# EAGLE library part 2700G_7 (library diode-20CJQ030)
Intel® 2700G7 Multimedia Graphic Accelerator with 16MB SDRAM 14 mm x 14 mm, 0.65 mm ball pitch 364 ball BGA package optimized for space constrained handheld devices Features: Advanced Packages -14 mm x 14 mm, 0.65 mm ball pitch, 364 ball BGA package optimized for space constrained handheld devices Low Power - Up to VGA (640x480x16 bpp) refresh from integrated frame buffer (2700G5 Multimedia Accelerator only) - Extensive clock gating of both registers and modules - Low voltage core (1.2 V) - Low voltage I/O (1.8 V) - 0.13 micron process technology - Partial and one-shot display refresh support Low Power, High Performance Video Acceleration - Accelerated MPEG 2 video decode, 720 x 480 resolution, 30+ fps - Accelerated MPEG 4 video decode, 640 x 480, 30+ fps - Accelerated WMV* video decode, 640 x 480, 30+ fps - Hardware accelerated Inverse Discrete Cosine Transforms (IDCT) - Hardware accelerated motion compensation - Hardware accelerated color space conversion - Hardware accelerated scaling Low Power, High Performance Graphics Acceleration - 2D and 3D acceleration - Up to 75 MHz, 32-bit graphics engine - 150M pixels per second (pps) fill rate for 2D - 831K triangles per second (tps) processing capability for 3D Packaged Memory Solutions - Integrated 704 KB on die memory - Stacked high-speed SDRAM for local memory - High-speed SDRAM local memory interface -- 16 MB SDRAM at 100 MHz -- 1.8 V SDRAM support -- Low-power SDRAM support Accelerated Dual Display - Simultaneous displays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
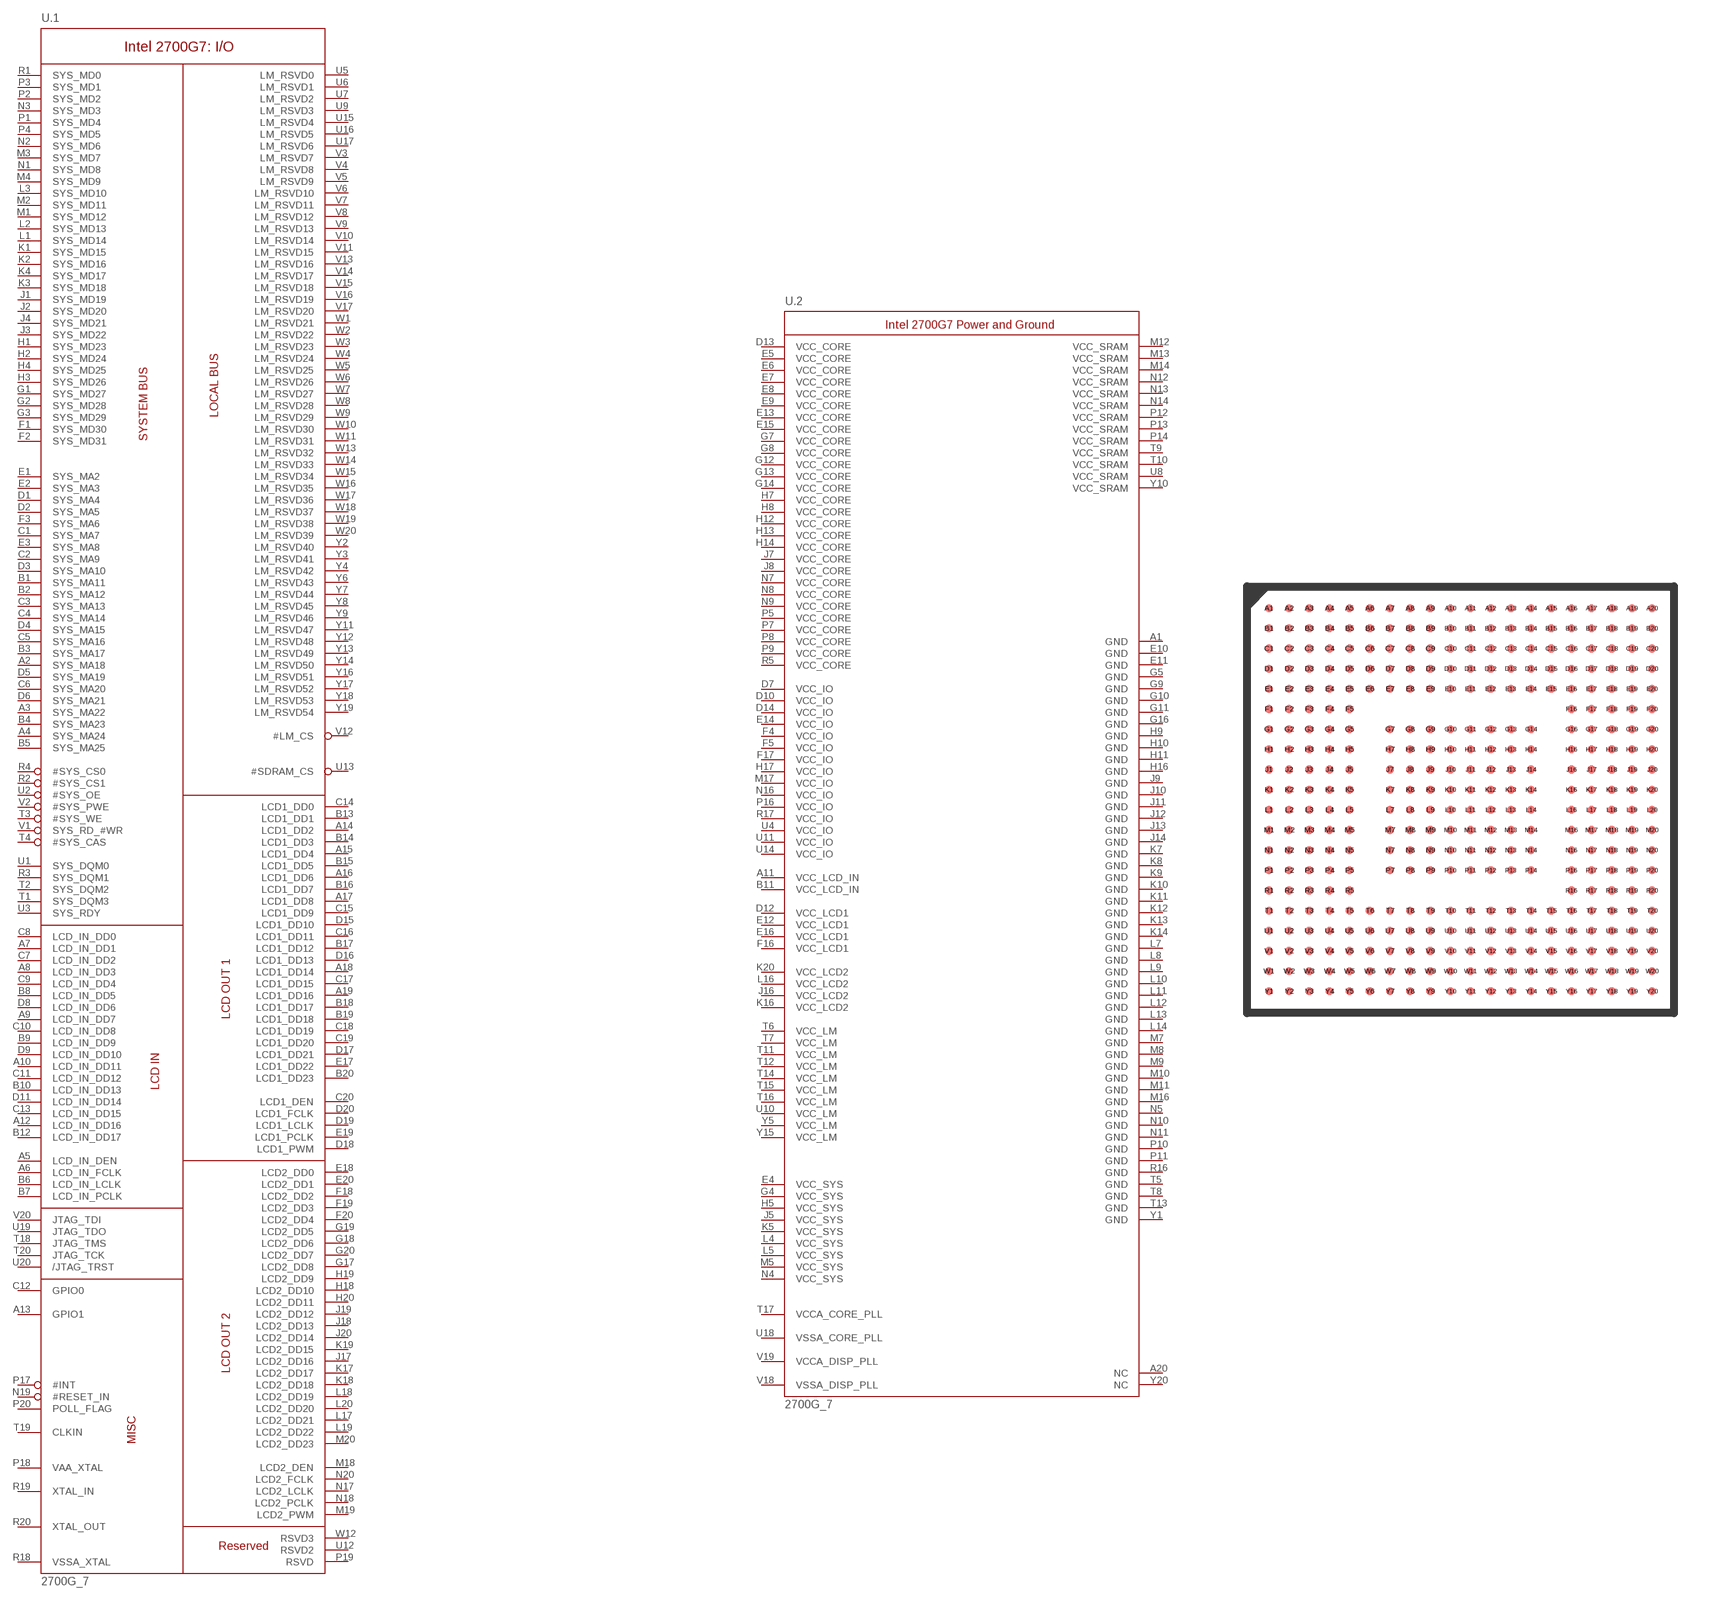
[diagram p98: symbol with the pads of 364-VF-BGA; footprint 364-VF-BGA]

Designator prefix U; gates .1=2700G7_PERIPHERALS .2=2700G7_POWER

## 2700G_7  [364-VF-BGA]
A1  .2:GND  pwr
A2  .1:SYS_MA18  in
A3  .1:SYS_MA22  in
A4  .1:SYS_MA24  in
A5  .1:LCD_IN_DEN  in
A6  .1:LCD_IN_FCLK  in
A7  .1:LCD_IN_DD1  in
A8  .1:LCD_IN_DD3  in
A9  .1:LCD_IN_DD7  in
A10  .1:LCD_IN_DD11  in
A11  .2:VCC_LCD_IN  pwr
A12  .1:LCD_IN_DD16  in
A13  .1:GPIO1
A14  .1:LCD1_DD2  out
A15  .1:LCD1_DD4  out
A16  .1:LCD1_DD6  out
A17  .1:LCD1_DD8  out
A18  .1:LCD1_DD14  out
A19  .1:LCD1_DD16  out
A20  .2:NC  nc
B1  .1:SYS_MA11  in
B2  .1:SYS_MA12  in
B3  .1:SYS_MA17  in
B4  .1:SYS_MA23  in
B5  .1:SYS_MA25  in
B6  .1:LCD_IN_LCLK  in
B7  .1:LCD_IN_PCLK  in
B8  .1:LCD_IN_DD5  in
B9  .1:LCD_IN_DD9  in
B10  .1:LCD_IN_DD13  in
B11  .2:VCC_LCD_IN  pwr
B12  .1:LCD_IN_DD17  in
B13  .1:LCD1_DD1  out
B14  .1:LCD1_DD3  out
B15  .1:LCD1_DD5  out
B16  .1:LCD1_DD7  out
B17  .1:LCD1_DD12  out
B18  .1:LCD1_DD17  out
B19  .1:LCD1_DD18  out
B20  .1:LCD1_DD23  out
C1  .1:SYS_MA7  in
C2  .1:SYS_MA9  in
C3  .1:SYS_MA13  in
C4  .1:SYS_MA14  in
C5  .1:SYS_MA16  in
C6  .1:SYS_MA20  in
C7  .1:LCD_IN_DD2  in
C8  .1:LCD_IN_DD0  in
C9  .1:LCD_IN_DD4  in
C10  .1:LCD_IN_DD8  in
C11  .1:LCD_IN_DD12  in
C12  .1:GPIO0
C13  .1:LCD_IN_DD15  in
C14  .1:LCD1_DD0  out
C15  .1:LCD1_DD9  out
C16  .1:LCD1_DD11  out
C17  .1:LCD1_DD15  out
C18  .1:LCD1_DD19  out
C19  .1:LCD1_DD20  out
C20  .1:LCD1_DEN  out
D1  .1:SYS_MA4  in
D2  .1:SYS_MA5  in
D3  .1:SYS_MA10  in
D4  .1:SYS_MA15  in
D5  .1:SYS_MA19  in
D6  .1:SYS_MA21  in
D7  .2:VCC_IO  pwr
D8  .1:LCD_IN_DD6  in
D9  .1:LCD_IN_DD10  in
D10  .2:VCC_IO  pwr
D11  .1:LCD_IN_DD14  in
D12  .2:VCC_LCD1  pwr
D13  .2:VCC_CORE  pwr
D14  .2:VCC_IO  pwr
D15  .1:LCD1_DD10  out
D16  .1:LCD1_DD13  out
D17  .1:LCD1_DD21  out
D18  .1:LCD1_PWM  out
D19  .1:LCD1_LCLK  out
D20  .1:LCD1_FCLK  out
E1  .1:SYS_MA2  in
E2  .1:SYS_MA3  in
E3  .1:SYS_MA8  in
E4  .2:VCC_SYS  pwr
E5  .2:VCC_CORE  pwr
E6  .2:VCC_CORE  pwr
E7  .2:VCC_CORE  pwr
E8  .2:VCC_CORE  pwr
E9  .2:VCC_CORE  pwr
E10  .2:GND  pwr
E11  .2:GND  pwr
E12  .2:VCC_LCD1  pwr
E13  .2:VCC_CORE  pwr
E14  .2:VCC_IO  pwr
E15  .2:VCC_CORE  pwr
E16  .2:VCC_LCD1  pwr
E17  .1:LCD1_DD22  out
E18  .1:LCD2_DD0  out
E19  .1:LCD1_PCLK  out
E20  .1:LCD2_DD1  out
F1  .1:SYS_MD30
F2  .1:SYS_MD31
F3  .1:SYS_MA6  in
F4  .2:VCC_IO  pwr
F5  .2:VCC_IO  pwr
F16  .2:VCC_LCD1  pwr
F17  .2:VCC_IO  pwr
F18  .1:LCD2_DD2  out
F19  .1:LCD2_DD3  out
F20  .1:LCD2_DD4  out
G1  .1:SYS_MD27
G2  .1:SYS_MD28
G3  .1:SYS_MD29
G4  .2:VCC_SYS  pwr
G5  .2:GND  pwr
G7  .2:VCC_CORE  pwr
G8  .2:VCC_CORE  pwr
G9  .2:GND  pwr
G10  .2:GND  pwr
G11  .2:GND  pwr
G12  .2:VCC_CORE  pwr
G13  .2:VCC_CORE  pwr
G14  .2:VCC_CORE  pwr
G16  .2:GND  pwr
G17  .1:LCD2_DD8  out
G18  .1:LCD2_DD6  out
G19  .1:LCD2_DD5  out
G20  .1:LCD2_DD7  out
H1  .1:SYS_MD23
H2  .1:SYS_MD24
H3  .1:SYS_MD26
H4  .1:SYS_MD25
H5  .2:VCC_SYS  pwr
H7  .2:VCC_CORE  pwr
H8  .2:VCC_CORE  pwr
H9  .2:GND  pwr
H10  .2:GND  pwr
H11  .2:GND  pwr
H12  .2:VCC_CORE  pwr
H13  .2:VCC_CORE  pwr
H14  .2:VCC_CORE  pwr
H16  .2:GND  pwr
H17  .2:VCC_IO  pwr
H18  .1:LCD2_DD10  out
H19  .1:LCD2_DD9  out
H20  .1:LCD2_DD11  out
J1  .1:SYS_MD19
J2  .1:SYS_MD20
J3  .1:SYS_MD22
J4  .1:SYS_MD21
J5  .2:VCC_SYS  pwr
J7  .2:VCC_CORE  pwr
J8  .2:VCC_CORE  pwr
J9  .2:GND  pwr
J10  .2:GND  pwr
J11  .2:GND  pwr
J12  .2:GND  pwr
J13  .2:GND  pwr
J14  .2:GND  pwr
J16  .2:VCC_LCD2  pwr
J17  .1:LCD2_DD16  out
J18  .1:LCD2_DD13  out
J19  .1:LCD2_DD12  out
J20  .1:LCD2_DD14  out
K1  .1:SYS_MD15
K2  .1:SYS_MD16
K3  .1:SYS_MD18
K4  .1:SYS_MD17
K5  .2:VCC_SYS  pwr
K7  .2:GND  pwr
K8  .2:GND  pwr
K9  .2:GND  pwr
K10  .2:GND  pwr
K11  .2:GND  pwr
K12  .2:GND  pwr
K13  .2:GND  pwr
K14  .2:GND  pwr
K16  .2:VCC_LCD2  pwr
K17  .1:LCD2_DD17  out
K18  .1:LCD2_DD18  out
K19  .1:LCD2_DD15  out
K20  .2:VCC_LCD2  pwr
L1  .1:SYS_MD14
L2  .1:SYS_MD13
L3  .1:SYS_MD10
L4  .2:VCC_SYS  pwr
L5  .2:VCC_SYS  pwr
L7  .2:GND  pwr
L8  .2:GND  pwr
L9  .2:GND  pwr
L10  .2:GND  pwr
L11  .2:GND  pwr
L12  .2:GND  pwr
L13  .2:GND  pwr
L14  .2:GND  pwr
L16  .2:VCC_LCD2  pwr
L17  .1:LCD2_DD21  out
L18  .1:LCD2_DD19  out
L19  .1:LCD2_DD22  out
L20  .1:LCD2_DD20  out
M1  .1:SYS_MD12
M2  .1:SYS_MD11
M3  .1:SYS_MD7
M4  .1:SYS_MD9
M5  .2:VCC_SYS  pwr
M7  .2:GND  pwr
M8  .2:GND  pwr
M9  .2:GND  pwr
M10  .2:GND  pwr
M11  .2:GND  pwr
M12  .2:VCC_SRAM  pwr
M13  .2:VCC_SRAM  pwr
M14  .2:VCC_SRAM  pwr
M16  .2:GND  pwr
M17  .2:VCC_IO  pwr
M18  .1:LCD2_DEN  out
M19  .1:LCD2_PWM  out
M20  .1:LCD2_DD23  out
N1  .1:SYS_MD8
N2  .1:SYS_MD6
N3  .1:SYS_MD3
N4  .2:VCC_SYS  pwr
N5  .2:GND  pwr
N7  .2:VCC_CORE  pwr
N8  .2:VCC_CORE  pwr
N9  .2:VCC_CORE  pwr
N10  .2:GND  pwr
N11  .2:GND  pwr
N12  .2:VCC_SRAM  pwr
N13  .2:VCC_SRAM  pwr
N14  .2:VCC_SRAM  pwr
N16  .2:VCC_IO  pwr
N17  .1:LCD2_LCLK  out
N18  .1:LCD2_PCLK  out
N19  .1:#RESET_IN  in
N20  .1:LCD2_FCLK  out
P1  .1:SYS_MD4
P2  .1:SYS_MD2
P3  .1:SYS_MD1
P4  .1:SYS_MD5
P5  .2:VCC_CORE  pwr
P7  .2:VCC_CORE  pwr
P8  .2:VCC_CORE  pwr
P9  .2:VCC_CORE  pwr
P10  .2:GND  pwr
P11  .2:GND  pwr
P12  .2:VCC_SRAM  pwr
P13  .2:VCC_SRAM  pwr
P14  .2:VCC_SRAM  pwr
P16  .2:VCC_IO  pwr
P17  .1:#INT  out
P18  .1:VAA_XTAL  pwr
P19  .1:RSVD  in
P20  .1:POLL_FLAG  out
R1  .1:SYS_MD0
R2  .1:#SYS_CS1  in
R3  .1:SYS_DQM1  in
R4  .1:#SYS_CS0  in
R5  .2:VCC_CORE  pwr
R16  .2:GND  pwr
R17  .2:VCC_IO  pwr
R18  .1:VSSA_XTAL  pwr
R19  .1:XTAL_IN  in
R20  .1:XTAL_OUT  out
T1  .1:SYS_DQM3  in
T2  .1:SYS_DQM2  in
T3  .1:#SYS_WE  in
T4  .1:#SYS_CAS  in
T5  .2:GND  pwr
T6  .2:VCC_LM  pwr
T7  .2:VCC_LM  pwr
T8  .2:GND  pwr
T9  .2:VCC_SRAM  pwr
T10  .2:VCC_SRAM  pwr
T11  .2:VCC_LM  pwr
T12  .2:VCC_LM  pwr
T13  .2:GND  pwr
T14  .2:VCC_LM  pwr
T15  .2:VCC_LM  pwr
T16  .2:VCC_LM  pwr
T17  .2:VCCA_CORE_PLL  pwr
T18  .1:JTAG_TMS  in
T19  .1:CLKIN  in
T20  .1:JTAG_TCK  in
U1  .1:SYS_DQM0  in
U2  .1:#SYS_OE  in
U3  .1:SYS_RDY  out
U4  .2:VCC_IO  pwr
U5  .1:LM_RSVD0
U6  .1:LM_RSVD1
U7  .1:LM_RSVD2
U8  .2:VCC_SRAM  pwr
U9  .1:LM_RSVD3
U10  .2:VCC_LM  pwr
U11  .2:VCC_IO  pwr
U12  .1:RSVD2  in
U13  .1:#SDRAM_CS  out
U14  .2:VCC_IO  pwr
U15  .1:LM_RSVD4
U16  .1:LM_RSVD5
U17  .1:LM_RSVD6
U18  .2:VSSA_CORE_PLL  pwr
U19  .1:JTAG_TDO  out
U20  .1:/JTAG_TRST  in
V1  .1:SYS_RD_#WR  in
V2  .1:#SYS_PWE  in
V3  .1:LM_RSVD7
V4  .1:LM_RSVD8
V5  .1:LM_RSVD9
V6  .1:LM_RSVD10
V7  .1:LM_RSVD11
V8  .1:LM_RSVD12
V9  .1:LM_RSVD13
V10  .1:LM_RSVD14
V11  .1:LM_RSVD15
V12  .1:#LM_CS  out
V13  .1:LM_RSVD16
V14  .1:LM_RSVD17
V15  .1:LM_RSVD18
V16  .1:LM_RSVD19
V17  .1:LM_RSVD20
V18  .2:VSSA_DISP_PLL  pwr
V19  .2:VCCA_DISP_PLL  pwr
V20  .1:JTAG_TDI  in
W1  .1:LM_RSVD21
W2  .1:LM_RSVD22
W3  .1:LM_RSVD23
W4  .1:LM_RSVD24
W5  .1:LM_RSVD25
W6  .1:LM_RSVD26
W7  .1:LM_RSVD27
W8  .1:LM_RSVD28
W9  .1:LM_RSVD29
W10  .1:LM_RSVD30
W11  .1:LM_RSVD31
W12  .1:RSVD3  in
W13  .1:LM_RSVD32  out
W14  .1:LM_RSVD33  out
W15  .1:LM_RSVD34  out
W16  .1:LM_RSVD35  out
W17  .1:LM_RSVD36  out
W18  .1:LM_RSVD37  out
W19  .1:LM_RSVD38  out
W20  .1:LM_RSVD39  out
Y1  .2:GND  pwr
Y2  .1:LM_RSVD40  out
Y3  .1:LM_RSVD41  out
Y4  .1:LM_RSVD42  out
Y5  .2:VCC_LM  pwr
Y6  .1:LM_RSVD43  out
Y7  .1:LM_RSVD44  out
Y8  .1:LM_RSVD45  out
Y9  .1:LM_RSVD46  out
Y10  .2:VCC_SRAM  pwr
Y11  .1:LM_RSVD47  out
Y12  .1:LM_RSVD48  out
Y13  .1:LM_RSVD49  out
Y14  .1:LM_RSVD50  out
Y15  .2:VCC_LM  pwr
Y16  .1:LM_RSVD51  out
Y17  .1:LM_RSVD52  out
Y18  .1:LM_RSVD53  out
Y19  .1:LM_RSVD54  out
Y20  .2:NC  nc

## Footprint 364-VF-BGA (pad centres in mm)
VF-BGA. Package 14 mm x 14 mm BGA. 364 balls spaced on a 0.65 mm ball grid (pitch) The ball diameter is 0.254 mm. (Design Guide of Intels 2700G3/5/7) Please send any comments to: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
smd 0.254 x 0.254: A1 -6.175,6.175; A2 -5.525,6.175; A3 -4.875,6.175; A4 -4.225,6.175; A5 -3.575,6.175; A6 -2.925,6.175; A7 -2.275,6.175; A8 -1.625,6.175; A9 -0.975,6.175; A10 -0.325,6.175; A11 0.325,6.175; A12 0.975,6.175; A13 1.625,6.175; A14 2.275,6.175; A15 2.925,6.175; A16 3.575,6.175; A17 4.225,6.175; A18 4.875,6.175; A19 5.525,6.175; A20 6.175,6.175; B1 -6.175,5.525; B2 -5.525,5.525; B3 -4.875,5.525; B4 -4.225,5.525; B5 -3.575,5.525; B6 -2.925,5.525; B7 -2.275,5.525; B8 -1.625,5.525; B9 -0.975,5.525; B10 -0.325,5.525; B11 0.325,5.525; B12 0.975,5.525; B13 1.625,5.525; B14 2.275,5.525; B15 2.925,5.525; B16 3.575,5.525; B17 4.225,5.525; B18 4.875,5.525; B19 5.525,5.525; B20 6.175,5.525; C1 -6.175,4.875; C2 -5.525,4.875; C3 -4.875,4.875; C4 -4.225,4.875; C5 -3.575,4.875; C6 -2.925,4.875; C7 -2.275,4.875; C8 -1.625,4.875; C9 -0.975,4.875; C10 -0.325,4.875; C11 0.325,4.875; C12 0.975,4.875; C13 1.625,4.875; C14 2.275,4.875; C15 2.925,4.875; C16 3.575,4.875; C17 4.225,4.875; C18 4.875,4.875; C19 5.525,4.875; C20 6.175,4.875; D1 -6.175,4.225; D2 -5.525,4.225; D3 -4.875,4.225; D4 -4.225,4.225; D5 -3.575,4.225; D6 -2.925,4.225; D7 -2.275,4.225; D8 -1.625,4.225; D9 -0.975,4.225; D10 -0.325,4.225; D11 0.325,4.225; D12 0.975,4.225; D13 1.625,4.225; D14 2.275,4.225; D15 2.925,4.225; D16 3.575,4.225; D17 4.225,4.225; D18 4.875,4.225; D19 5.525,4.225; D20 6.175,4.225; E1 -6.175,3.575; E2 -5.525,3.575; E3 -4.875,3.575; E4 -4.225,3.575; E5 -3.575,3.575; E6 -2.925,3.575; E7 -2.275,3.575; E8 -1.625,3.575; E9 -0.975,3.575; E10 -0.325,3.575; E11 0.325,3.575; E12 0.975,3.575; E13 1.625,3.575; E14 2.275,3.575; E15 2.925,3.575; E16 3.575,3.575; E17 4.225,3.575; E18 4.875,3.575; E19 5.525,3.575; E20 6.175,3.575; F1 -6.175,2.925; F2 -5.525,2.925; F3 -4.875,2.925; F4 -4.225,2.925; F5 -3.575,2.925; F16 3.575,2.925; F17 4.225,2.925; F18 4.875,2.925; F19 5.525,2.925; F20 6.175,2.925; G1 -6.175,2.275; G2 -5.525,2.275; G3 -4.875,2.275; G4 -4.225,2.275; G5 -3.575,2.275; G7 -2.275,2.275; G8 -1.625,2.275; G9 -0.975,2.275; G10 -0.325,2.275; G11 0.325,2.275; G12 0.975,2.275; G13 1.625,2.275; G14 2.275,2.275; G16 3.575,2.275; G17 4.225,2.275; G18 4.875,2.275; G19 5.525,2.275; G20 6.175,2.275; H1 -6.175,1.625; H2 -5.525,1.625; H3 -4.875,1.625; H4 -4.225,1.625; H5 -3.575,1.625; H7 -2.275,1.625; H8 -1.625,1.625; H9 -0.975,1.625; H10 -0.325,1.625; H11 0.325,1.625; H12 0.975,1.625; H13 1.625,1.625; H14 2.275,1.625; H16 3.575,1.625; H17 4.225,1.625; H18 4.875,1.625; H19 5.525,1.625; H20 6.175,1.625; J1 -6.175,0.975; J2 -5.525,0.975; J3 -4.875,0.975; J4 -4.225,0.975; J5 -3.575,0.975; J7 -2.275,0.975; J8 -1.625,0.975; J9 -0.975,0.975; J10 -0.325,0.975; J11 0.325,0.975; J12 0.975,0.975; J13 1.625,0.975; J14 2.275,0.975; J16 3.575,0.975; J17 4.225,0.975; J18 4.875,0.975; J19 5.525,0.975; J20 6.175,0.975; K1 -6.175,0.325; K2 -5.525,0.325; K3 -4.875,0.325; K4 -4.225,0.325; K5 -3.575,0.325; K7 -2.275,0.325; K8 -1.625,0.325; K9 -0.975,0.325; K10 -0.325,0.325; K11 0.325,0.325; K12 0.975,0.325; K13 1.625,0.325; K14 2.275,0.325; K16 3.575,0.325; K17 4.225,0.325; K18 4.875,0.325; K19 5.525,0.325; K20 6.175,0.325; L1 -6.175,-0.325; L2 -5.525,-0.325; L3 -4.875,-0.325; L4 -4.225,-0.325; L5 -3.575,-0.325; L7 -2.275,-0.325; L8 -1.625,-0.325; L9 -0.975,-0.325; L10 -0.325,-0.325; L11 0.325,-0.325; L12 0.975,-0.325; L13 1.625,-0.325; L14 2.275,-0.325; L16 3.575,-0.325; L17 4.225,-0.325; L18 4.875,-0.325; L19 5.525,-0.325; L20 6.175,-0.325; M1 -6.175,-0.975; M2 -5.525,-0.975; M3 -4.875,-0.975; M4 -4.225,-0.975; M5 -3.575,-0.975; M7 -2.275,-0.975; M8 -1.625,-0.975; M9 -0.975,-0.975; M10 -0.325,-0.975; M11 0.325,-0.975; M12 0.975,-0.975; M13 1.625,-0.975; M14 2.275,-0.975; M16 3.575,-0.975; M17 4.225,-0.975; M18 4.875,-0.975; M19 5.525,-0.975; M20 6.175,-0.975; N1 -6.175,-1.625; N2 -5.525,-1.625; N3 -4.875,-1.625; N4 -4.225,-1.625; N5 -3.575,-1.625; N7 -2.275,-1.625; N8 -1.625,-1.625; N9 -0.975,-1.625; N10 -0.325,-1.625; N11 0.325,-1.625; N12 0.975,-1.625; N13 1.625,-1.625; N14 2.275,-1.625; N16 3.575,-1.625; N17 4.225,-1.625; N18 4.875,-1.625; N19 5.525,-1.625; N20 6.175,-1.625; P1 -6.175,-2.275; P2 -5.525,-2.275; P3 -4.875,-2.275; P4 -4.225,-2.275; P5 -3.575,-2.275; P7 -2.275,-2.275; P8 -1.625,-2.275; P9 -0.975,-2.275; P10 -0.325,-2.275; P11 0.325,-2.275; P12 0.975,-2.275; P13 1.625,-2.275; P14 2.275,-2.275; P16 3.575,-2.275; P17 4.225,-2.275; P18 4.875,-2.275; P19 5.525,-2.275; P20 6.175,-2.275; R1 -6.175,-2.925; R2 -5.525,-2.925; R3 -4.875,-2.925; R4 -4.225,-2.925; R5 -3.575,-2.925; R16 3.575,-2.925; R17 4.225,-2.925; R18 4.875,-2.925; R19 5.525,-2.925; R20 6.175,-2.925; T1 -6.175,-3.575; T2 -5.525,-3.575; T3 -4.875,-3.575; T4 -4.225,-3.575; T5 -3.575,-3.575; T6 -2.925,-3.575; T7 -2.275,-3.575; T8 -1.625,-3.575; T9 -0.975,-3.575; T10 -0.325,-3.575; T11 0.325,-3.575; T12 0.975,-3.575; T13 1.625,-3.575; T14 2.275,-3.575; T15 2.925,-3.575; T16 3.575,-3.575; T17 4.225,-3.575; T18 4.875,-3.575; T19 5.525,-3.575; T20 6.175,-3.575; U1 -6.175,-4.225; U2 -5.525,-4.225; U3 -4.875,-4.225; U4 -4.225,-4.225; U5 -3.575,-4.225; U6 -2.925,-4.225; U7 -2.275,-4.225; U8 -1.625,-4.225; U9 -0.975,-4.225; U10 -0.325,-4.225; U11 0.325,-4.225; U12 0.975,-4.225; U13 1.625,-4.225; U14 2.275,-4.225; U15 2.925,-4.225; U16 3.575,-4.225; U17 4.225,-4.225; U18 4.875,-4.225; U19 5.525,-4.225; U20 6.175,-4.225; V1 -6.175,-4.875; V2 -5.525,-4.875; V3 -4.875,-4.875; V4 -4.225,-4.875; V5 -3.575,-4.875; V6 -2.925,-4.875; V7 -2.275,-4.875; V8 -1.625,-4.875; V9 -0.975,-4.875; V10 -0.325,-4.875; V11 0.325,-4.875; V12 0.975,-4.875; V13 1.625,-4.875; V14 2.275,-4.875; V15 2.925,-4.875; V16 3.575,-4.875; V17 4.225,-4.875; V18 4.875,-4.875; V19 5.525,-4.875; V20 6.175,-4.875; W1 -6.175,-5.525; W2 -5.525,-5.525; W3 -4.875,-5.525; W4 -4.225,-5.525; W5 -3.575,-5.525; W6 -2.925,-5.525; W7 -2.275,-5.525; W8 -1.625,-5.525; W9 -0.975,-5.525; W10 -0.325,-5.525; W11 0.325,-5.525; W12 0.975,-5.525; W13 1.625,-5.525; W14 2.275,-5.525; W15 2.925,-5.525; W16 3.575,-5.525; W17 4.225,-5.525; W18 4.875,-5.525; W19 5.525,-5.525; W20 6.175,-5.525; Y1 -6.175,-6.175; Y2 -5.525,-6.175; Y3 -4.875,-6.175; Y4 -4.225,-6.175; Y5 -3.575,-6.175; Y6 -2.925,-6.175; Y7 -2.275,-6.175; Y8 -1.625,-6.175; Y9 -0.975,-6.175; Y10 -0.325,-6.175; Y11 0.325,-6.175; Y12 0.975,-6.175; Y13 1.625,-6.175; Y14 2.275,-6.175; Y15 2.925,-6.175; Y16 3.575,-6.175; Y17 4.225,-6.175; Y18 4.875,-6.175; Y19 5.525,-6.175; Y20 6.175,-6.175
